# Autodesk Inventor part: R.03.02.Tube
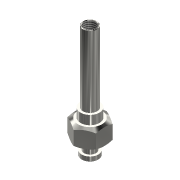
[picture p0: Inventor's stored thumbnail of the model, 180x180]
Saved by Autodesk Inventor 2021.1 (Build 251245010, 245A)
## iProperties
Created: 2021-02
Part Number: R.03.02.Tube
Material: Stainless Steel
Document SubType Name: Modeling
Designer: Михальчик
Density: 8 g/cm^3
Appearance: Silver
Author: Михальчик
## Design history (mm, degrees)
sketch "Sketch1"
  geometry: L1 (0, 0)-(8.575, 0); L2 (0, 0)-(2, 0); L3 (2, 0)-(2, -3.5); L4 (2, -3.5)-(0, -3.5); L5 (0, -3.5)-(0, 0); L6 (2, 0)-(5.75, 0); L7 (5.75, 0)-(5.75, -2.5); L8 (5.75, -2.5)-(2, -2.5); L9 (2, -2.5)-(2, 0); L10 (5.75, 0)-(13.75, 0); L11 (13.75, 0)-(13.75, -7); L12 (13.75, -7)-(5.75, -7); L13 (5.75, -7)-(5.75, 0); L14 (13.75, 0)-(17.5, 0); L15 (17.5, 0)-(17.5, -4); L16 (17.5, -4)-(13.75, -4); L17 (13.75, -4)-(13.75, 0); L18 (17.5, 0)-(47.5, 0); L19 (47.5, 0)-(47.5, -3); L20 (47.5, -3)-(17.5, -3); L21 (17.5, -3)-(17.5, 0); L22 (0, 0)-(10, 0); L23 (10, 0)-(10, -1.5); L24 (10, -1.5)-(0, -1.5); L25 (0, -1.5)-(0, 0); L26 (47.5, 0)-(37.5, 0); L27 (37.5, 0)-(37.5, -2.5); L28 (37.5, -2.5)-(47.5, -2.5); L29 (47.5, -2.5)-(47.5, 0); L30 (37.5, -2.5)-(35.998, 0); L31 (37.5, 0)-(10, 0); L32 (10, 0)-(10, -1); L33 (10, -1)-(37.5, -1); L34 (37.5, -1)-(37.5, 0); L35 (13.75, -5)-(12.595, -7); L36 (6.905, -7)-(5.75, -5); 8 further points
  constraints: 72 end point, 16 parallel, 9 horizontal, 8 perpendicular, 6 point on line, 1 equal length
  dimensions: "d0" = 14 diameter of L12 L1; "d1" = 7 diameter of L4 L1; "d2" = 5 diameter of L8 L1; "d3" = 3 distance between parallel lines of L18 L20; "d4" = 8 diameter of L16 L1; "d5" = 47.5 distance between parallel lines of L19 L5; "d6" = 3.75 distance between parallel lines of L7 L3; "d7" = 8 distance between parallel lines of L11 L13; "d8" = 3.75 distance of L15.end L16.end; "d9" = 2 distance of L3.end L4.end; "d11" = 3 diameter of L24 L1; "d12" = 2.5 distance between parallel lines of L10 L28; "d13" = 59 deg angle of L18 L30; "d14" = 10 distance of L27.end L28.end; "d15" = 1 distance between parallel lines of L14 L33; "d16" = 10 distance of L23.end L24.end; "d20" = 30 deg angle of L11 L35; "d21" = 30 deg angle of L13 L36; "d22" = 2 vertical distance of L35.start L35.end
revolve "Revolution1" sketch "Sketch1" stored, may be unused: angle "d10" = 90 deg
sketch "Sketch2"
  geometry: L1 (0, 6.928)-(6, 3.464); L2 (6, 3.464)-(6, -3.464); L3 (6, -3.464)-(0, -6.928); L4 (0, -6.928)-(-6, -3.464); L5 (-6, -3.464)-(-6, 3.464); L6 (-6, 3.464)-(0, 6.928); C1 r 7 at (0, 0); C2 r 7 at (0, 0) reference; 2 further points
  constraints: 12 end point, 2 coincident, 2 concentric, 1 centre point, 1 vertical, 13 other
  dimensions: "d17" = 12 distance between parallel lines of L2 L5
extrude "Extrusion1" cut sketch "Sketch2" distance "d18" = 10; taper "d19" = 0 deg
chamfer "Chamfer1" distance "d23" = 0.2; stored, may be unused: second distance "d24" = 2, angle "d25" = 45 deg
thread "Thread1" dims "d26" = 9.8, "d27" = 0
body "Solid1"
